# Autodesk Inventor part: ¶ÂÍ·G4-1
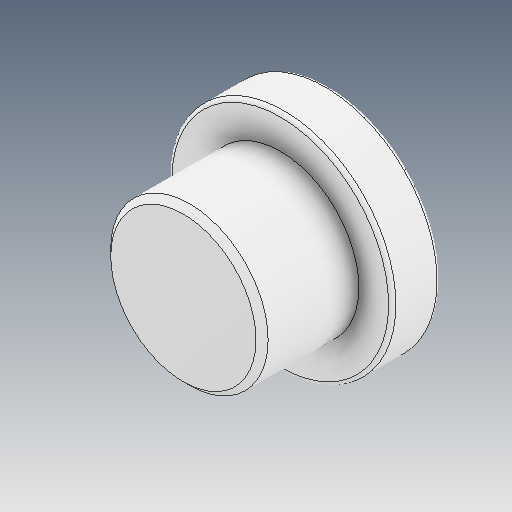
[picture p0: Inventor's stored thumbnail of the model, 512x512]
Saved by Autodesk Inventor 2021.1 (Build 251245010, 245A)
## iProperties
Created: 2021-06
Part Number: ¶ÂÍ·G4-1
Material: Ogólny
Document SubType Name: Modeling
Designer: user
Density: 1 g/cm^3
Appearance: Domyślna
Author: user
Revision Number: ÈÎºÎ
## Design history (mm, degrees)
feature "µ¹½Ç2"
node "Bryła1"
